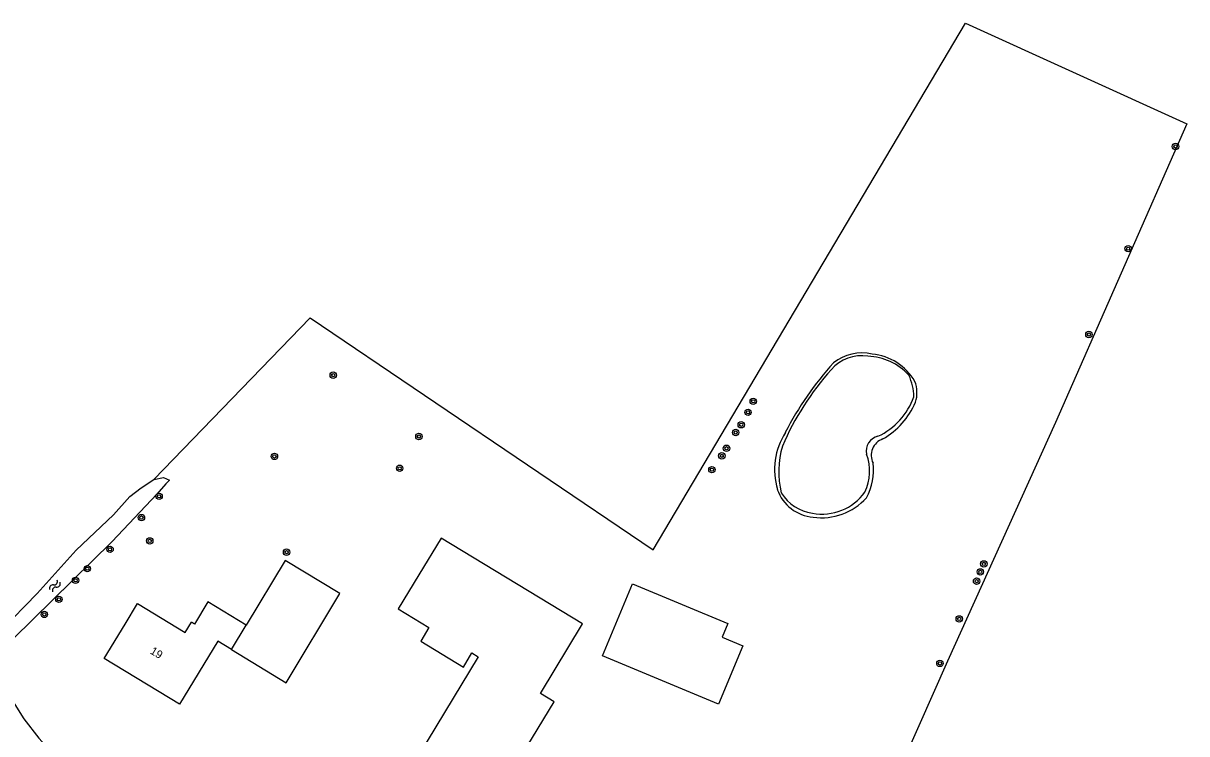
# Model space of a CAD drawing. Extents: x 133000 to 136000, y 400500 to 403500.
# Drawn here: x 134543.9 to 134689.3, y 400674.4 to 400763.2 of the extents above; entities that cross this region are included whole.
import ezdxf

# ---------------------------------------------------------------- set-up
doc = ezdxf.new("R2010")
doc.units = 0
for name, color, linetype in [('gg-anno-huisnummerreeks BGT', 7, 'Continuous'), ('gg-bbg-bijgebouw', 7, 'Continuous'), ('gg-bbg-gedigitaliseerde bebouwing', 7, 'Continuous'), ('gg-bbg-gedigitaliseerde bijgebouw', 7, 'Continuous'), ('gg-bbg-hoofdgebouw', 7, 'Continuous'), ('gg-bbg-tussenscheiding', 7, 'Continuous'), ('gg-knt-bronhoudergrens', 7, 'Continuous'), ('gg-kntw-bovenkant insteek waterloop', 7, 'Continuous'), ('gg-kntw-waterlijn', 7, 'Continuous'), ('gt-symb-boom', 7, 'Continuous'), ('gt-symb-watersymbool', 7, 'Continuous')]:
    doc.layers.add(name, color=color, linetype=linetype)

# ---------------------------------------------------------------- blocks, each defined once
blk = doc.blocks.new('gt0-BOOM')
at = {"layer": 'gt-symb-boom'}
for radius in [0.4, 0.2]:
    blk.add_circle((0, 0), radius, dxfattribs=at)
blk = doc.blocks.new('gt0-WA')
at = {"layer": 'gt-symb-watersymbool'}
for centre, start, end in [((-0.32, 0.02), 28.0725, 151.9275), ((0.43, 0.42), 208.0725, 331.9275), ((-0.32, -0.43), 28.0725, 151.9275), ((0.43, -0.03), 208.0725, 331.9275)]:
    blk.add_arc(centre, 0.425, start, end, dxfattribs=at)

msp = doc.modelspace()

# ---------------------------------------------------------------- linework, layer by layer
at = {"layer": 'gg-bbg-bijgebouw'}
msp.add_lwpolyline([(134569.88, 400684.95), (134576.71, 400680.79), (134583.43, 400691.92), (134576.6, 400696.08)], dxfattribs=at)
at = {"layer": 'gg-bbg-gedigitaliseerde bebouwing'}
msp.add_lwpolyline([(134571.71, 400687.99), (134566.94, 400690.89), (134565.25, 400688.11), (134564.87, 400688.34)], dxfattribs=at)
at = {"layer": 'gg-bbg-gedigitaliseerde bijgebouw'}
msp.add_line((134576.6, 400696.08), (134571.71, 400687.99), dxfattribs=at)
msp.add_lwpolyline([(134616.26, 400684.16), (134620.01, 400693.15), (134631.92, 400688.19), (134631.2, 400686.47), (134633.77, 400685.4), (134630.74, 400678.13), (134616.26, 400684.16)], dxfattribs=at)
at = {"layer": 'gg-bbg-hoofdgebouw'}
msp.add_line((134569.88, 400684.95), (134568.16, 400685.99), dxfattribs=at)
for points in [[(134593.3, 400694.29), (134590.72, 400690.01), (134594.55, 400687.7), (134593.52, 400685.99), (134598.87, 400682.75), (134599.93, 400684.51), (134600.7, 400684.04), (134588.08, 400663.16), (134597.48, 400657.46), (134600.07, 400661.74), (134610.2, 400678.42), (134608.49, 400679.46), (134613.75, 400688.14), (134596.08, 400698.86), (134593.3, 400694.29)], [(134556.57, 400688.11), (134558.13, 400690.68), (134564.09, 400687.05), (134564.87, 400688.34)], [(134568.16, 400685.99), (134563.37, 400678.12), (134553.97, 400683.84), (134556.57, 400688.11)]]:
    msp.add_lwpolyline(points, dxfattribs=at)
at = {"layer": 'gg-bbg-tussenscheiding'}
msp.add_line((134569.88, 400684.95), (134571.71, 400687.99), dxfattribs=at)
at = {"layer": 'gg-knt-bronhoudergrens'}
msp.add_line((134560.18, 400706.18), (134579.72, 400726.38), dxfattribs=at)
msp.add_lwpolyline([(134579.72, 400726.38), (134622.59, 400697.4), (134661.61, 400763.15), (134689.26, 400750.59), (134681.06, 400731.93), (134672.86, 400713.28), (134659.36, 400683.51), (134634.29, 400626.97)], dxfattribs=at)
at = {"layer": 'gg-kntw-bovenkant insteek waterloop'}
for points in [[(134539.07, 400685.51), (134539.58, 400686.08), (134541.03, 400687.27), (134545.58, 400691.95), (134550.46, 400697.36), (134555.15, 400701.78), (134557.19, 400704.05), (134558.59, 400705.15), (134560.18, 400706.18)], [(134560.18, 400706.18), (134561.4, 400706.43), (134562.13, 400706.1), (134561.66, 400705.62), (134560.56, 400704.36), (134554.96, 400698.43), (134542.6, 400686.26), (134540.86, 400684.23), (134540.67, 400683.33), (134541.25, 400681.41), (134542.39, 400678.75), (134543.94, 400676.29), (134545.8, 400673.86), (134547.81, 400671.67), (134550.14, 400669.77), (134556.92, 400665.14), (134563.77, 400661.11), (134572.83, 400656.08)]]:
    msp.add_lwpolyline(points, dxfattribs=at)
for centre, radius, start, end in [((134648.67, 400716.28), 5.71, 77.092, 128.495), ((134649.28, 400714.92), 6.95, 30.2414, 84.4891), ((134674.51, 400693.98), 39.76, 137.6802, 152.9788), ((134651.63, 400717.02), 3.92, 342.3345, 21.0219), ((134646.55, 400719.55), 9.56, 299.5972, 337.0784), ((134646.48, 400707.38), 8.73, 147.7623, 196.3026), ((134651.99, 400709.2), 2.16, 109.2936, 206.665), ((134642.97, 400707.32), 7.14, 331.3674, 7.283), ((134642.97, 400706.62), 5.16, 199.0614, 265.5916), ((134643.63, 400708.94), 7.54, 261.9657, 318.0281)]:
    msp.add_arc(centre, radius, start, end, dxfattribs=at)
at = {"layer": 'gg-kntw-waterlijn'}
for centre, radius, start, end in [((134648.62, 400716.61), 5.02, 80.9799, 139.1767), ((134649.08, 400714.11), 7.47, 43.0586, 87.4691), ((134671.28, 400696.27), 35.47, 138.2409, 156.6103), ((134648.25, 400716.35), 6.91, 1.3049, 24.4174), ((134647.05, 400719.38), 8.6, 294.9261, 340.4802), ((134651.1, 400709.74), 1.89, 102.9797, 192.7407), ((134649.37, 400707.17), 11.11, 163.3782, 193.8762), ((134643.61, 400707.21), 6.03, 334.3336, 20.5053), ((134643.25, 400707.4), 5.49, 211.7856, 261.8669), ((134643.66, 400708.52), 6.66, 259.7816, 323.9625)]:
    msp.add_arc(centre, radius, start, end, dxfattribs=at)

# ---------------------------------------------------------------- block references
at = {"layer": 'gt-symb-boom'}
for p in [(134687.86, 400747.77), (134681.94, 400735), (134677.03, 400724.29), (134582.59, 400719.21), (134635.08, 400715.94), (134634.43, 400714.56), (134633.58, 400713.01), (134593.3, 400711.55), (134632.89, 400712.05), (134631.74, 400710.08), (134575.24, 400709.06), (134631.16, 400709.13), (134590.9, 400707.58), (134629.92, 400707.41), (134560.83, 400704.07), (134558.62, 400701.42), (134559.66, 400698.51), (134554.7, 400697.46), (134576.76, 400697.1), (134551.86, 400695.04), (134663.9, 400695.64), (134550.39, 400693.59), (134663, 400693.48), (134663.46, 400694.64), (134548.31, 400691.21), (134546.48, 400689.33), (134660.83, 400688.77), (134658.41, 400683.21)]:
    msp.add_blockref('gt0-BOOM', p, dxfattribs=at)
at = {"layer": 'gt-symb-watersymbool', "rotation": 52.19034788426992}
msp.add_blockref('gt0-WA', (134547.77, 400692.84), dxfattribs=at)

# ---------------------------------------------------------------- texts
at = {"layer": 'gg-anno-huisnummerreeks BGT'}
msp.add_text('19', height=1, rotation=328.7, dxfattribs=at).set_placement((134559.62, 400684.5))

doc.saveas('drawing.dxf')
